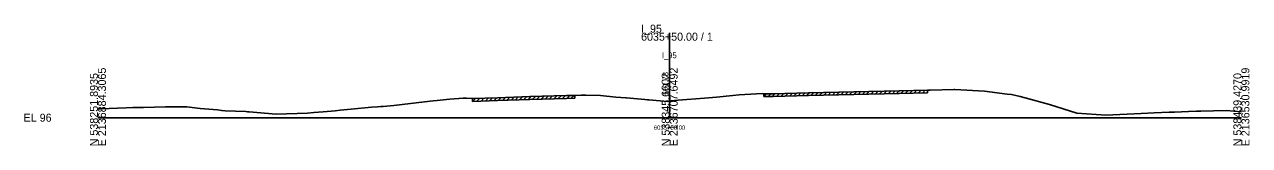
# Model space of a CAD drawing. Extents: x -12534 to 3403, y -1332 to 21983.
# Drawn here: x 1974.3 to 2402.8, y 490.3 to 532.5 of the extents above; entities that cross this region are included whole.
import ezdxf

# ---------------------------------------------------------------- set-up
doc = ezdxf.new("R2010")
doc.units = 0
for name, color, linetype in [('RD_GPK_XS_Cell', 7, 'Continuous'), ('RD_XS_ExGround', 7, 'Continuous'), ('RD_XS_ExPaveRet', 7, 'Continuous'), ('RD_XS_TX_Baseline', 7, 'Continuous'), ('RD_XS_TX_Elev_EX', 7, 'Continuous'), ('RD_XS_TX_Station', 7, 'Continuous')]:
    doc.layers.add(name, color=color, linetype=linetype)

msp = doc.modelspace()

# ---------------------------------------------------------------- linework, layer by layer
at = {"layer": 'RD_GPK_XS_Cell'}
for p, q in [((2200, 500), (2200, 529.69)), ((2000, 500), (2200, 500)), ((2200, 500), (2400, 500))]:
    msp.add_line(p, q, dxfattribs=at)
at = {"layer": 'RD_XS_ExGround'}
msp.add_lwpolyline([(2000, 503.05), (2000.95, 503.1), (2009.86, 503.45), (2012.19, 503.6), (2015.91, 503.62), (2023.69, 503.74), (2029.1, 503.84), (2031.15, 503.79), (2035.75, 503.24), (2041.88, 502.72), (2043.31, 502.46), (2044.53, 502.37), (2051.71, 502.13), (2052.32, 502.07), (2052.9, 502.05), (2062.38, 501.23), (2073.25, 501.62), (2075.49, 501.76), (2078.73, 502.03), (2083.04, 502.4), (2084.78, 502.58), (2088.64, 502.96), (2095.73, 503.64), (2097.84, 503.81), (2098.97, 503.9), (2099.83, 503.96), (2103.49, 504.31), (2114.2, 505.5), (2117.25, 505.86), (2118.62, 506), (2121.93, 506.36), (2123.1, 506.46), (2127.78, 506.77), (2128.95, 506.79), (2131.02, 506.69), (2139.79, 506.96), (2151.11, 507.41), (2163.94, 507.72), (2166.83, 507.81), (2169.02, 507.92), (2170.69, 507.92), (2175.82, 507.7), (2181.22, 507.23), (2184.61, 506.98), (2184.91, 506.94), (2191.32, 506.32), (2192.3, 506.21), (2192.7, 506.21), (2199.2, 505.66), (2200, 505.78), (2200.46, 505.86), (2202.94, 506.07), (2212.13, 506.82), (2213.6, 506.95), (2216.34, 507.18), (2222.09, 507.81), (2224.3, 508), (2230.4, 508.33), (2232.38, 508.41), (2232.91, 508.38), (2236.24, 508.39), (2248.51, 508.73), (2280.24, 509.44), (2290.16, 509.65), (2291.08, 509.56), (2299.44, 509.9), (2299.77, 509.87), (2310.15, 509.25), (2318.01, 508.26), (2319.61, 508.05), (2322.57, 507.36), (2323.92, 507.11), (2324.37, 506.97), (2332.87, 504.59), (2342.45, 501.59), (2352.64, 500.94), (2364.93, 501.49), (2369.53, 501.7), (2374.74, 501.9), (2376.62, 501.95), (2381.46, 502.19), (2384.35, 502.34), (2385.81, 502.26), (2394.68, 502.52), (2400, 502.01)], dxfattribs=at)
at = {"layer": 'RD_XS_ExPaveRet'}
for p, q in [((2131.02, 505.69), (2132.05, 506.72)), ((2131.02, 505.69), (2131.02, 506.69)), ((2131.02, 505.69), (2139.79, 505.96)), ((2132.52, 505.74), (2133.55, 506.77)), ((2134.02, 505.79), (2135.05, 506.82)), ((2135.52, 505.83), (2136.55, 506.86)), ((2137.02, 505.88), (2138.05, 506.91)), ((2138.52, 505.93), (2139.55, 506.96)), ((2139.79, 505.96), (2151.11, 506.41)), ((2140.02, 505.97), (2141.06, 507.01)), ((2141.52, 506.03), (2142.56, 507.07)), ((2143.02, 506.09), (2144.06, 507.13)), ((2144.52, 506.15), (2145.56, 507.19)), ((2146.02, 506.21), (2147.06, 507.25)), ((2147.52, 506.27), (2148.56, 507.31)), ((2149.02, 506.33), (2150.06, 507.37)), ((2150.52, 506.39), (2151.55, 507.42)), ((2151.11, 506.41), (2163.94, 506.72)), ((2152.02, 506.43), (2153.04, 507.46)), ((2153.52, 506.47), (2154.54, 507.49)), ((2155.02, 506.5), (2156.04, 507.53)), ((2156.52, 506.54), (2157.54, 507.56)), ((2158.02, 506.58), (2159.04, 507.6)), ((2159.52, 506.61), (2160.54, 507.64)), ((2161.02, 506.65), (2162.04, 507.67)), ((2162.52, 506.68), (2163.54, 507.71)), ((2163.94, 506.72), (2166.83, 506.81)), ((2164.02, 506.72), (2165.05, 507.75)), ((2165.52, 506.77), (2166.55, 507.8)), ((2166.83, 507.81), (2166.83, 506.81)), ((2232.91, 507.38), (2233.91, 508.38)), ((2232.91, 507.38), (2232.91, 508.38)), ((2232.91, 507.38), (2236.24, 507.39)), ((2234.41, 507.38), (2235.41, 508.39)), ((2235.91, 507.39), (2236.93, 508.41)), ((2236.24, 507.39), (2248.51, 507.73)), ((2237.41, 507.42), (2238.44, 508.45)), ((2238.91, 507.46), (2239.94, 508.49)), ((2240.41, 507.5), (2241.44, 508.53)), ((2241.91, 507.55), (2242.94, 508.58)), ((2243.41, 507.59), (2244.44, 508.62)), ((2244.91, 507.63), (2245.94, 508.66)), ((2246.41, 507.67), (2247.44, 508.7)), ((2247.91, 507.71), (2248.93, 508.74)), ((2248.51, 507.73), (2280.24, 508.44)), ((2249.41, 507.75), (2250.43, 508.77)), ((2250.91, 507.79), (2251.93, 508.81)), ((2252.41, 507.82), (2253.43, 508.84)), ((2253.91, 507.85), (2254.93, 508.87)), ((2255.41, 507.89), (2256.43, 508.91)), ((2256.91, 507.92), (2257.93, 508.94)), ((2258.41, 507.95), (2259.43, 508.97)), ((2259.91, 507.99), (2260.93, 509.01)), ((2261.41, 508.02), (2262.43, 509.04)), ((2262.91, 508.05), (2263.93, 509.07)), ((2264.41, 508.09), (2265.43, 509.11)), ((2265.91, 508.12), (2266.93, 509.14)), ((2267.41, 508.15), (2268.43, 509.17)), ((2268.91, 508.19), (2269.93, 509.21)), ((2270.41, 508.22), (2271.43, 509.24)), ((2271.91, 508.25), (2272.93, 509.28)), ((2273.41, 508.29), (2274.43, 509.31)), ((2274.91, 508.32), (2275.93, 509.34)), ((2276.41, 508.35), (2277.43, 509.38)), ((2277.91, 508.39), (2278.93, 509.41)), ((2279.41, 508.42), (2280.43, 509.44)), ((2280.24, 508.44), (2290.16, 508.65)), ((2280.91, 508.45), (2281.93, 509.47)), ((2282.41, 508.48), (2283.43, 509.5)), ((2283.91, 508.51), (2284.93, 509.54)), ((2285.41, 508.55), (2286.43, 509.57)), ((2286.91, 508.58), (2287.93, 509.6)), ((2288.41, 508.61), (2289.43, 509.63)), ((2290.16, 509.65), (2290.16, 508.65))]:
    msp.add_line(p, q, dxfattribs=at)

# ---------------------------------------------------------------- texts
at = {"layer": 'RD_GPK_XS_Cell'}
for s, p in [('I_95', (2190, 529.69)), ('6035+50.00 / 1', (2190, 526.89)), ('EL 96', (1974, 498.6))]:
    msp.add_text(s, height=2.8, dxfattribs=at).set_placement(p)
for s, p in [('N 538251.8935', (2000, 490)), ('E 2136884.3065', (2002.8, 490)), ('N 538345.6602', (2200, 490)), ('E 2136707.6492', (2202.8, 490)), ('N 538439.4270', (2400, 490)), ('E 2136530.9919', (2402.8, 490))]:
    msp.add_text(s, height=2.8, rotation=90, dxfattribs=at).set_placement(p)
at = {"layer": 'RD_XS_TX_Baseline'}
msp.add_text('I_95', height=2, dxfattribs=at).set_placement((2197.28, 520.78))
at = {"layer": 'RD_XS_TX_Elev_EX'}
msp.add_text('101.78', height=2, rotation=90, dxfattribs=at).set_placement((2199.5, 507.78))
at = {"layer": 'RD_XS_TX_Station'}
msp.add_text('6035+50.00', height=1.5, dxfattribs=at).set_placement((2194.45, 495.78))

doc.saveas('drawing.dxf')
